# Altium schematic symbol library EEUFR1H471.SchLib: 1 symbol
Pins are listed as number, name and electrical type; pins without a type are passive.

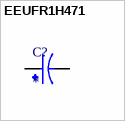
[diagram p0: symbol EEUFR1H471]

## EEUFR1H471
designator C?
470ÂµF 50V Aluminum Electrolytic Capacitors Radial, Can 10000 Hrs @ 105Â°C; MP: EEUFR1H471; MF: Panasonic
footprint CAPPRD500W60D1250H2000
pins: N, P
